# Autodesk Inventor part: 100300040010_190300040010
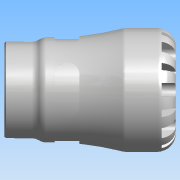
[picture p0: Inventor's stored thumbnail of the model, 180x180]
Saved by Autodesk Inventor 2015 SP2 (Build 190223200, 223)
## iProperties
Created: 2016-12
Part Number: 100300040010_190300040010
Material: PVC-Piping
Description: PLASSON FEMALE ADAPTOR 40X1" SERIES 1
Document SubType Name: Modeling
Designer: KIM
Mass: 664.223 g
Surface Area: 733.008 cm^2
Volume: 474.445 cm^3
Density: 1.4 g/cm^3
Appearance: Smooth - White
Author: KIM
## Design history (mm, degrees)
derived "1003.ipt"
feature "Solid1::1003.ipt"
tag "TaggingFeature1"
body "Solid1"
other parameters: "d0" = 97, "d1" = 29.4, "d8" = 59.5, "d13" = 8, "d14" = 8, "d15" = 0, "d17" = 360 deg, "d19" = 8 deg, "d20" = 0.8, "d21" = 0.8, "d22" = 8 deg, "d24" = 0, "d26" = 360 deg, "d32" = 7, "d33" = 7, "d39" = 0.90873, "d42" = 30.291, "d43" = 54.6, "d46" = 3.33333, "d47" = 21, "d48" = 28.77645, "d50" = 1.98, "d51" = 0.7, "d54" = 14, "d55" = 8.8, "d57" = 15.68, "d58" = 0, "d68" = 360 deg, "d72" = 0.8, "d74" = 0, "d76" = 11.9, "H_" = 97, "Rp" = 30.291, "l_2" = 21, "d9" = 10, "d49" = 6
